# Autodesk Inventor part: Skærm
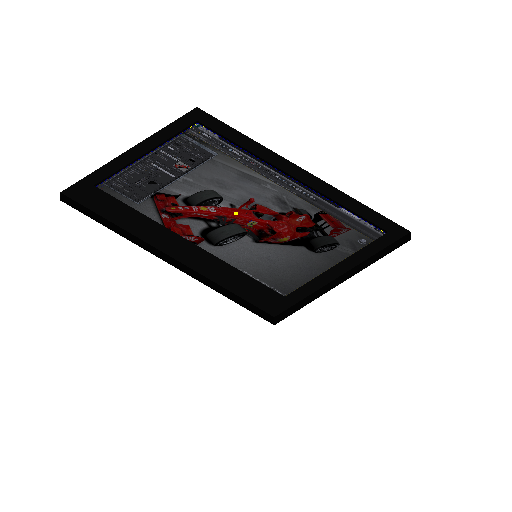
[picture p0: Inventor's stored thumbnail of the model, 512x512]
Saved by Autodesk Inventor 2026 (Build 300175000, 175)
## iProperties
Created: 2013-10
Part Number: Skærm
Material: Polypropylene
Document SubType Name: Modeling
Designer: Lars Bertram Pedersen
Density: 0.899 g/cm^3
Appearance: Anodized - Black
Mass: 4402.57 g
Surface Area: 5208.51 cm^2
Volume: 4897.19 cm^3
Stock Number: 2000
Author: Lars Bertram Pedersen
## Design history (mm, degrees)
sketch "Sketch1"
  geometry: L1 (295, -195)-(-295, -195); L2 (-295, -195)-(-295, 195); L3 (-295, 195)-(295, 195); L4 (295, 195)-(295, -195); L5 (295, -195)-(-295, 195); L6 (-295, -195)-(295, 195); 1 further point
  constraints: 12 end point, 2 midpoint, 2 parallel, 1 horizontal, 1 perpendicular
  dimensions: "d0" = 590 distance of L2.end L3.end; "d1" = 390 distance of L3.end L1.start
extrude "Extrusion1" new body sketch "Sketch1" distance "d2" = 30; taper "d3" = 0 deg
sketch "Sketch2"
  geometry: L1 (295, 195)-(295, -195) reference; L2 (295, -195)-(-295, -195) reference; L3 (-295, -195)-(-295, 195) reference; L4 (-295, 195)-(295, 195) reference; L5 (263, -132)-(-263, -132); L6 (-263, -132)-(-263, 163); L7 (-263, 163)-(263, 163); L8 (263, 163)-(263, -132); 1 further point
  constraints: 8 end point, 2 parallel, 1 horizontal, 1 perpendicular
  dimensions: "d6" = 32 distance between parallel lines of L4 L7; "d7" = 32 distance between parallel lines of L3 L6; "d8" = 32 distance between parallel lines of L1 L8; "d9" = 295 distance between parallel lines of L7 L5
extrude "Extrusion2" cut sketch "Sketch2" distance "d10" = 6; taper "d11" = 0 deg
sketch "Sketch6"
  geometry: L1 (253, 122)-(-253, 122); L2 (-253, 122)-(-253, -122); L3 (-253, -122)-(253, -122); L4 (253, -122)-(253, 122); L5 (253, 122)-(-253, -122); L6 (-253, 122)-(253, -122); L7 (-263, -132)-(263, -132) reference; L8 (263, -132)-(263, 163) reference; L9 (263, 163)-(-263, 163) reference; L10 (-263, 163)-(-263, -132) reference; L11 (-295, -195)-(295, -195) reference; L12 (295, -195)-(295, 195) reference; L13 (295, 195)-(-295, 195) reference; L14 (-295, 195)-(-295, -195) reference; 1 further point
  constraints: 12 end point, 2 midpoint, 2 parallel, 1 horizontal, 1 perpendicular
  dimensions: "d37" = 10 distance between parallel lines of L4 L8; "d38" = 10 distance between parallel lines of L3 L7 (= d37)
extrude "Extrusion3" cut sketch "Sketch6" distance "d39" = 10; taper "d40" = 0 deg
fillet "Fillet1" dims "d41" = 5
sketch "Sketch3"
  geometry: L1 (263, -132)-(-263, -132) reference; L2 (263, 163)-(263, -132) reference; L3 (-263, 163)-(263, 163) reference; L4 (-263, -132)-(-263, 163) reference; L5 (-263, 163)-(266.291, 163); L6 (266.291, 163)-(266.291, -156.838); L7 (266.291, -156.838)-(-263, -156.838); L8 (-263, -156.838)-(-263, 163); 1 further point; 1 other entity
  constraints: 1 horizontal, 2 other
  node "Image1"
sketch "Sketch5" dims "d1" = 390
  geometry: L1 (125, 70)-(-125, -70); L2 (125, -70)-(125, 70); 3 further points
  constraints: 4 end point, 2 horizontal alignment, 2 vertical alignment, 1 coincident, 1 midpoint, 1 vertical
  dimensions: "d31" = 250 distance of L1.start point (-125, 70); "d32" = 140 distance of L2.start L1.start
hole "Hole1" sketch "Sketch5" diameter "d24" = 5.13397; stored, may be unused: countersink angle "d28" = 90 deg, drill point angle "d30" = 118 deg; dims "d25" = 15, "d26" = 4, "d27" = 2, "d29" = 18
fillet "Fillet2" dims "d43" = 2
body "Solid1"
sketch "Sketch7"
  geometry: L1 (-263, 163)-(263, 163); L2 (263, 163)-(263, -154.854); L3 (263, -154.854)-(-263, -154.854); L4 (-263, -154.854)-(-263, 163); 3 further points; 1 other entity
  constraints: 2 coincident, 2 other
node "Projected Loop2"
node "Image2"
node "Project Cut Edges1"
